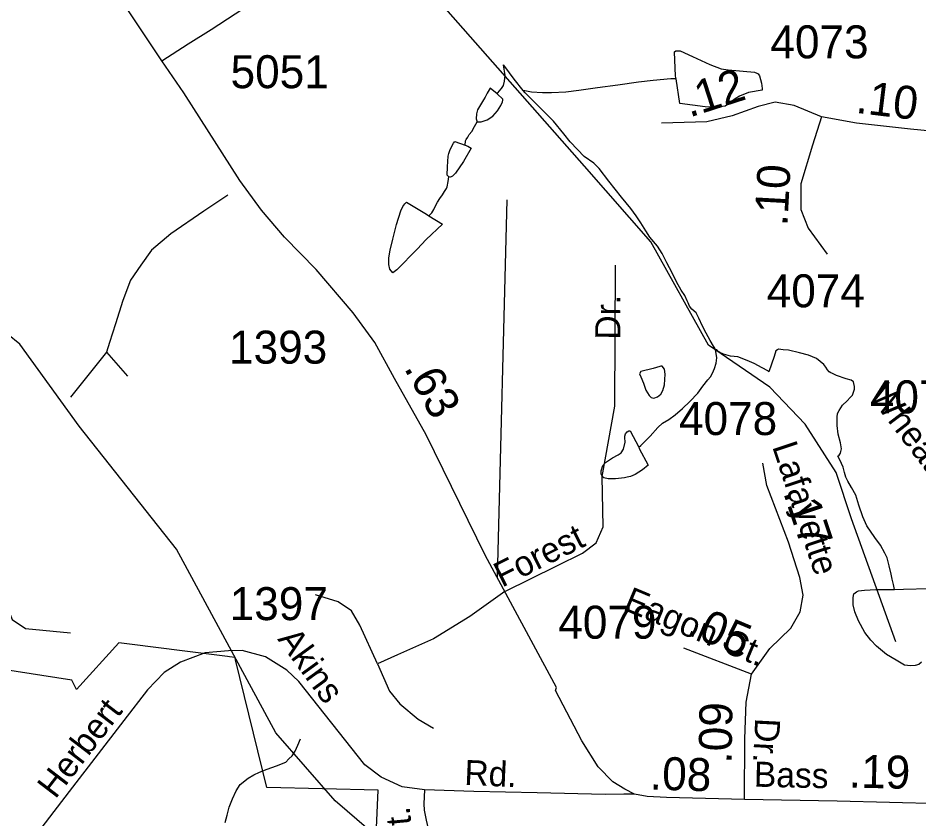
# Model space of a CAD drawing. Extents: x 2001466 to 2224147, y 644118 to 847247.
# Drawn here: x 2059578 to 2062991, y 683500 to 686536 of the extents above; entities that cross this region are included whole.
import ezdxf

# ---------------------------------------------------------------- set-up
doc = ezdxf.new("R2010")
doc.units = 0
for name, color, linetype in [('Exist Boundary Political City Limit New', 7, 'Continuous'), ('Exist Hydrographic Misc Water Feature', 7, 'Continuous'), ('Exist Road Non-System Type 51', 7, 'Continuous'), ('Exist Road Non-System Type 51 Label', 7, 'Continuous'), ('Exist Road Secondary Mileage Hundredths English Label', 7, 'Continuous'), ('Exist Road Secondary Type 51 Attributed', 7, 'Continuous'), ('Exist Road Secondary Type 51 Label', 7, 'Continuous'), ('Exist Road Secondary Type 51 Number Label', 7, 'Continuous'), ('Map Preparation Boundary City Limit Buffer Line', 7, 'Continuous')]:
    doc.layers.add(name, color=color, linetype=linetype)

msp = doc.modelspace()

# ---------------------------------------------------------------- linework, layer by layer
at = {"layer": 'Exist Boundary Political City Limit New'}
for points in [[(2059959.2, 684167.6), (2059798.8, 683990.9), (2059781, 684026.7), (2058611.8, 684208.8), (2058604, 684033.6), (2056704.1, 683944.6), (2056239.2, 683932.6), (2056313, 684129.7), (2054722.9, 684120.6)], [(2060928.9, 683323.6), (2060941.4, 683609.2), (2060520.2, 683619.2), (2060401.9, 684103.4), (2060399.8, 684112.5), (2060379.1, 684115.3), (2060370.9, 684116.2), (2060351.6, 684118.6), (2060209.2, 684136.4), (2060000, 684162.6), (2059959.2, 684167.6)]]:
    msp.add_lwpolyline(points, dxfattribs=at)
at = {"layer": 'Exist Hydrographic Misc Water Feature'}
for points in [[(2061723.1, 685974.1), (2061047.8, 686743), (2060930.9, 687066.9), (2060913.9, 687316.5), (2060779.8, 687657.2), (2060746, 687799), (2060762, 688274.4), (2060820, 688476.6), (2060795, 688674), (2060743.9, 688825.9), (2060693.9, 689125.6), (2060668.9, 689149)], [(2062070.4, 686305.7), (2062068.5, 686315.7), (2062064.4, 686408.1), (2062070.2, 686412.1), (2062086.4, 686412), (2062132.5, 686390.1), (2062198.5, 686360.2), (2062242, 686344.2), (2062268.3, 686340.2), (2062368.1, 686330.4), (2062376.5, 686326.7), (2062382.1, 686324.6), (2062386.4, 686316.7), (2062394.4, 686288.7), (2062396.6, 686268.5), (2062396.4, 686262.4), (2062344.5, 686254.5), (2062310.7, 686240.5), (2062294.5, 686230.4), (2062284.3, 686222.2), (2062268.7, 686210.4), (2062256.8, 686202.4), (2062246.5, 686200.3), (2062234.8, 686198.1), (2062180.3, 686200.2), (2062084.5, 686211.9), (2062070.4, 686305.7)], [(2061392.7, 686248.7), (2061400.7, 686258.8), (2061408.7, 686268.6), (2061416.3, 686280.8), (2061420.6, 686296.8), (2061422.6, 686318.8), (2061416.5, 686358.6)], [(2061490.7, 686261), (2061456.9, 686304.7), (2061422.4, 686352.9), (2061416.5, 686358.6)], [(2062070.4, 686305.7), (2062050.5, 686305.9), (2061984.3, 686299.7), (2061928.5, 686293.6), (2061850.4, 686281.5), (2061772.7, 686271.4), (2061702.5, 686261.3), (2061652.7, 686255.1), (2061598.8, 686253.1), (2061564.7, 686253), (2061522.5, 686254.9), (2061490.7, 686261)], [(2061392.7, 686248.7), (2061366.7, 686270.5), (2061354.8, 686250.8), (2061347, 686236.6), (2061340.6, 686226.6), (2061318.9, 686188.5), (2061315, 686172.5), (2061312.7, 686154.5), (2061317.2, 686142.5)], [(2061317.2, 686142.5), (2061321.1, 686142.7), (2061332.8, 686142.6), (2061354.8, 686150.6), (2061376.9, 686164.7), (2061394.7, 686184.7), (2061407, 686204.7), (2061412.8, 686218.8), (2061414.6, 686224.7), (2061414.4, 686228.7), (2061392.7, 686248.7)], [(2062220.3, 685280.4), (2062218, 685284.4), (2062212.1, 685292.6), (2062200, 685314.3), (2062184.4, 685342.2), (2062170.5, 685368.2), (2062156.3, 685398.4), (2062146.1, 685418.2), (2062130.1, 685432.4), (2062121.9, 685444.2), (2062116.3, 685456.4), (2062112, 685464.3), (2062103.8, 685484.2), (2062089.9, 685504.2), (2062071.6, 685536.1), (2062055.6, 685570.2), (2062035.7, 685608.1), (2062017.9, 685644), (2061999.6, 685672), (2061971.6, 685705.8), (2061955.6, 685729.7), (2061937.7, 685759.6), (2061919.5, 685785.9), (2061899.6, 685813.7), (2061863.5, 685857.7), (2061815.3, 685917.3), (2061779, 685965.4), (2061758.9, 685985.5), (2061722.8, 686011.2), (2061697, 686037.5), (2061668.9, 686067.3), (2061644.9, 686097.2), (2061606.8, 686145.3), (2061554.5, 686197), (2061498.7, 686252.9), (2061490.7, 686261)], [(2061271.1, 686054.6), (2061273.4, 686070.5), (2061275.2, 686076.3), (2061281.1, 686084.3), (2061287.1, 686094.3), (2061296.7, 686106.7), (2061307, 686124.6), (2061317.2, 686142.5)], [(2061209.4, 685934.5), (2061203.2, 685940.3), (2061205.1, 685972.5), (2061207.1, 686012.4), (2061209.2, 686022.6), (2061215.3, 686038.3), (2061227, 686062.5), (2061233, 686068.5), (2061271.1, 686054.6)], [(2061271.1, 686054.6), (2061281.1, 686050.6), (2061294.9, 686042.4), (2061264.9, 685992.6), (2061235.2, 685948.5), (2061223.3, 685936.5), (2061215.5, 685932.4), (2061209.4, 685934.5)], [(2062902.7, 684172.4), (2062734.8, 684638.4), (2062676.7, 684813.5), (2062559.9, 684996.4), (2062425.7, 685136.8), (2062192.8, 685295.9), (2061974.8, 685687.4), (2061723.1, 685974.1)], [(2061133.7, 685786.2), (2061139.9, 685792.2), (2061145.4, 685798.2), (2061153.4, 685810.4), (2061159.6, 685824.5), (2061167.3, 685838.3), (2061175.3, 685852.5), (2061185.4, 685866.4), (2061193.2, 685878.2), (2061201.2, 685890.4), (2061203.4, 685896.5), (2061207.1, 685916.2), (2061209.4, 685934.5)], [(2061079.9, 683310.6), (2060778.8, 683569.3), (2060553.8, 683826.5), (2060177.8, 684523.2), (2059809.9, 684989.9), (2059584.8, 685299.6), (2059442.9, 685414.1), (2059116.8, 685830.8), (2058824.8, 685813.8)], [(2061133.7, 685786.2), (2061185.8, 685754.4), (2061123.9, 685696.4), (2061089.8, 685660.2), (2061012.1, 685582), (2060997.8, 685570), (2060986.1, 685583.9), (2060981.8, 685601.9), (2060982, 685627.9), (2060987.9, 685656.2), (2060997.8, 685698.1), (2061011.9, 685754), (2061027.3, 685806), (2061035.5, 685822.2), (2061043.5, 685831.9), (2061049.6, 685838.3), (2061125.3, 685792.3), (2061133.7, 685786.2)], [(2061929.1, 684910), (2061937.3, 684916), (2061949.2, 684928), (2061973, 684952), (2062000.9, 684983.9), (2062018.9, 685000.2), (2062042.9, 685014), (2062066.7, 685032.3), (2062094.6, 685056.5), (2062122.7, 685082.2), (2062152.6, 685114.2), (2062172.3, 685140.4), (2062190.3, 685164.4), (2062200.4, 685176.3), (2062208.8, 685190.5), (2062216.4, 685208.3), (2062222.3, 685228.5), (2062224.4, 685248.5), (2062220.3, 685280.4)], [(2062422.5, 685195), (2062418.4, 685198.8), (2062396.6, 685210.7), (2062366.5, 685226.5), (2062340.4, 685238.6), (2062304.6, 685252.6), (2062276.5, 685254.4), (2062250, 685262.5), (2062236.3, 685268.6), (2062230.5, 685272.3), (2062224.4, 685278.5), (2062220.3, 685280.4)], [(2062682.9, 684875.6), (2062689, 684879.5), (2062692.9, 684887.5), (2062694.8, 684893.3), (2062696.8, 684903.5), (2062692.9, 684925.6), (2062684.5, 684959.3), (2062681, 684991.5), (2062680.8, 685023.2), (2062682.7, 685037.5), (2062688.4, 685049.2), (2062700.7, 685069.2), (2062718.8, 685085.6), (2062730.5, 685097.6), (2062738.5, 685107.3), (2062746.4, 685129.6), (2062746.4, 685139.3), (2062744.2, 685151.4), (2062742.1, 685157.4), (2062734.4, 685163.5), (2062714.5, 685169.3), (2062678.2, 685181.3), (2062662.6, 685189.4), (2062656.4, 685191.1), (2062650.3, 685195.3), (2062644.3, 685203.1), (2062638.4, 685213.3), (2062630.4, 685223.1), (2062602.1, 685245.2), (2062572.6, 685259), (2062538.1, 685267), (2062496.5, 685277), (2062476, 685278.9), (2062458.4, 685280.8), (2062454.2, 685278.9), (2062448.1, 685275), (2062442.4, 685252.8), (2062422.5, 685195)], [(2061984.3, 685208.2), (2061936.5, 685196), (2061932.4, 685187.7), (2061936.5, 685175.7), (2061947, 685151.9), (2061956.6, 685126.1), (2061968.5, 685106), (2061976.5, 685097.9), (2061986.9, 685095.9), (2062000.7, 685099.9), (2062012.6, 685110.3), (2062020.6, 685124.1), (2062026.7, 685146.3), (2062028.8, 685186.1), (2062026.5, 685205.9), (2062018.3, 685216.1), (2062012.4, 685216.1), (2062008.7, 685215.9), (2061984.3, 685208.2)], [(2061929.1, 684910), (2061931.2, 684904), (2061965.4, 684842), (2061943.3, 684823.9), (2061915.6, 684805.8), (2061897.3, 684798), (2061885.4, 684795.7), (2061875.4, 684794), (2061841.6, 684789.8), (2061813.5, 684789.6), (2061797.1, 684793.7), (2061791.3, 684797.8), (2061787, 684807.8), (2061787.4, 684819.5), (2061793.4, 684839.7), (2061803.4, 684851.6), (2061829.3, 684869.5), (2061851.4, 684880), (2061862.9, 684888), (2061871.3, 684901.7), (2061877.2, 684928), (2061876.8, 684945.9), (2061877, 684951.9), (2061879.1, 684959.7), (2061884.8, 684967.8), (2061891, 684971.8), (2061896.9, 684972.1), (2061929.1, 684910)], [(2062897.8, 684370.1), (2062893.9, 684389.7), (2062889.6, 684409.9), (2062885.9, 684427.9), (2062877.7, 684460), (2062869.9, 684489.9), (2062861.7, 684507.8), (2062845.5, 684537.8), (2062823.8, 684567.5), (2062793.2, 684611.9), (2062777.6, 684645.5), (2062763.3, 684689.4), (2062751.4, 684727.8), (2062735, 684757.4), (2062721.2, 684781.4), (2062713.4, 684795.6), (2062709.1, 684813.6), (2062703.2, 684833.6), (2062691.1, 684861.4), (2062682.9, 684875.6)], [(2063000.3, 684094.2), (2062990.5, 684086.4), (2062976.1, 684082), (2062958.5, 684080.3), (2062936.5, 684083.9), (2062904.1, 684101.8), (2062868.2, 684123.9), (2062830.3, 684156), (2062808, 684177.7), (2062786.2, 684207.7), (2062762, 684251.6), (2062748.3, 684285.7), (2062741.9, 684311.8), (2062741.9, 684339.8), (2062743.8, 684353.7), (2062753.6, 684361.5), (2062762, 684365.5), (2062784, 684367.9), (2062827.6, 684369.8), (2062897.8, 684370.1)], [(2062897.8, 684370.1), (2062931.8, 684371.8), (2063029.8, 684374)], [(2060362.1, 683487.4), (2060370.1, 683515.4), (2060378.1, 683545.4), (2060389.8, 683577.3), (2060403.7, 683607.2), (2060419.5, 683631.2), (2060449.5, 683655.4), (2060471.6, 683667.5), (2060491.9, 683677.4), (2060521.4, 683689.6), (2060557.5, 683701.6), (2060591.8, 683715.4), (2060603.7, 683727.8), (2060615.8, 683739.8), (2060627.2, 683757.9), (2060637.3, 683779.9), (2060647.3, 683803.9)]]:
    msp.add_lwpolyline(points, dxfattribs=at)
at = {"layer": 'Exist Road Non-System Type 51'}
for p, q in [((2061429.2, 685847.7), (2061392.3, 684417.1)), ((2059912.5, 685269.2), (2059776.1, 685098.6)), ((2059912.5, 685269.2), (2059992.1, 685178.2))]:
    msp.add_line(p, q, dxfattribs=at)
for points in [[(2060372.6, 685864.3), (2060282.1, 685803.9), (2060157, 685718.6), (2060083.1, 685656), (2060043.3, 685599.1), (2060003.5, 685542.3), (2059975.1, 685465.5), (2059946.7, 685377.3), (2059923.9, 685306.2), (2059912.5, 685269.2)], [(2061421.8, 684362.2), (2061619.2, 684459.5), (2061715.8, 684507.8), (2061768.4, 684547.6), (2061794, 684607.4), (2061791.2, 684797.9), (2061838.1, 685065.2), (2061840.9, 685599.9)], [(2061421.8, 684362.2), (2061288.8, 684268.2), (2061151.9, 684183), (2061015, 684122.1), (2060938.9, 684088.6)], [(2060938.9, 684088.6), (2060872, 684234.7), (2060841.6, 684289.5), (2060789.9, 684323), (2060704.7, 684350.4)], [(2059532.3, 684313.5), (2059555.5, 684256.8), (2059605.7, 684222.1), (2059776.8, 684206.6)], [(2060938.9, 684088.6), (2060984.6, 683985.1), (2061024.1, 683936.4), (2061094.1, 683878.5), (2061151.9, 683845.1)], [(2061118, 683610.8), (2061114.4, 683558.1), (2061115.9, 683534.1), (2061123.7, 683495.6), (2061130.8, 683462.9), (2061140.7, 683434.4), (2061155, 683394.6), (2061179.1, 683336.2), (2061193.3, 683303.5)]]:
    msp.add_lwpolyline(points, dxfattribs=at)
at = {"layer": 'Exist Road Secondary Type 51 Attributed'}
for points in [[(2060123, 686374.3), (2060221.8, 686438.6), (2060309.9, 686493.1), (2060400.7, 686552.7), (2060489.8, 686612.8), (2060530.2, 686653.2), (2060551.6, 686681.7), (2060576.5, 686719.7), (2060602.6, 686770.8), (2060613.3, 686816), (2060618.1, 686854), (2060618.1, 686893.2), (2060614.5, 686924.1), (2060606.2, 686976.3), (2060590.7, 687019.1), (2060539.7, 687090.3), (2060458.4, 687196.7)], [(2060123, 686374.3), (2060036.3, 686503.2), (2059829.6, 686816.6)], [(2061913.2, 683594.9), (2061876.2, 683613.8), (2061831, 683641.4), (2061775.8, 683698.5), (2061713, 683796.4), (2061613.9, 683987.3), (2061617.4, 683998.9), (2061347.6, 684500.2), (2061123.5, 684955.8), (2061003.6, 685170.5), (2060929.4, 685306.3), (2060847.4, 685418.4), (2060706.9, 685583.4), (2060587, 685705), (2060500.2, 685807.6), (2060418.2, 685919.8), (2060205.2, 686252.1), (2060123, 686374.3)], [(2062621, 686161.8), (2062518.4, 686204.4), (2062445.8, 686217), (2062381.1, 686201.2), (2062283.3, 686164.9), (2062187.4, 686142.8), (2062015.4, 686137.3)], [(2062621, 686161.8), (2062587, 686054.4), (2062543.6, 685908.3), (2062543.2, 685810.4), (2062571.6, 685739.3), (2062642.7, 685641.4)], [(2063141.7, 686097), (2062958.6, 686114.4), (2062753.5, 686138.1), (2062621, 686161.8)], [(2062356.6, 684048.9), (2062426.1, 684146.8), (2062505.8, 684224.2), (2062540.5, 684285.8), (2062551.5, 684348.9), (2062538.9, 684415.3), (2062496.3, 684549.5), (2062415, 684764.2), (2062399.2, 684849.5)], [(2061913.2, 683594.9), (2061873, 683594.3), (2061802.1, 683593.7), (2061544.6, 683599.5), (2061304.3, 683605.1), (2061118, 683610.8), (2061032.6, 683622.2), (2060953, 683659.2), (2060891.9, 683706.2), (2060641.8, 684022.1), (2060595.4, 684064.1), (2060515.8, 684114.8), (2060427.4, 684139.5), (2060375.3, 684138), (2060286.9, 684130.8), (2060192.8, 684094.5), (2060131.9, 684055.4), (2060068.2, 683990.2), (2059978.4, 683874.3), (2059771.3, 683604.7), (2059621.9, 683410.2)], [(2062356.6, 684048.9), (2062099.4, 684148.4)], [(2062329.2, 683574.2), (2062331.4, 683804.2), (2062336.1, 683943.1), (2062356.6, 684048.9)], [(2062329.2, 683574.2), (2062034.3, 683581.7), (2061961.5, 683586.1), (2061913.2, 683594.9)], [(2063286, 683551.6), (2063077.7, 683557.9), (2062681.2, 683567.9), (2062329.2, 683574.2)]]:
    msp.add_lwpolyline(points, dxfattribs=at)
at = {"layer": 'Map Preparation Boundary City Limit Buffer Line'}
for points in [[(2059959.2, 684167.6), (2059798.8, 683990.9), (2059781, 684026.7), (2058611.8, 684208.8), (2058604, 684033.6), (2056704.1, 683944.6), (2056239.2, 683932.6), (2056313, 684129.7), (2054722.9, 684120.6)], [(2060928.9, 683323.6), (2060941.4, 683609.2), (2060520.2, 683619.2), (2060401.9, 684103.4), (2060399.8, 684112.5), (2060379.1, 684115.3), (2060370.9, 684116.2), (2060351.6, 684118.6), (2060209.2, 684136.4), (2060000, 684162.6), (2059959.2, 684167.6)]]:
    msp.add_lwpolyline(points, dxfattribs=at)

# ---------------------------------------------------------------- texts
at = {"layer": 'Exist Road Non-System Type 51 Label'}
for s, rotation, p in [('Dr.', 89.6954, (2061859, 685317.2)), ('Forest', 26.5752, (2061411, 684376.3)), (' St.', 95.2551, (2061078.6, 683360.5))]:
    msp.add_text(s, height=95, rotation=rotation, dxfattribs=at).set_placement(p)
at = {"layer": 'Exist Road Secondary Mileage Hundredths English Label'}
for s, rotation, p in [('.12', 17.9188, (2062121.1, 686158.5)), ('.10', 353.0737, (2062748.5, 686177.3)), ('.10', 86.8209, (2062491.9, 685746.1)), ('.63', 299.1804, (2061038, 685209.9)), ('.17', 288.3673, (2062475.4, 684738.1)), ('.05', 337.2765, (2062106.6, 684201.6)), ('.09', 89.0837, (2062280.7, 683709.7)), ('.08', 358.1516, (2061969.9, 683612.4)), ('.19', 358.7298, (2062724, 683619.7))]:
    msp.add_text(s, height=125, rotation=rotation, dxfattribs=at).set_placement(p)
at = {"layer": 'Exist Road Secondary Type 51 Label'}
for s, rotation, p in [('Wheatridge Dr.', 307.3933, (2062796.7, 685106.3)), ('Lafayette', 288.3673, (2062433.9, 684912.3)), ('Eagon Ct.', 337.2765, (2061866.3, 684294.7)), ('Akins', 306.0157, (2060558.7, 684181.6)), ('Herbert', 52.5129, (2059719.1, 683573.2)), ('Dr.', 267.0735, (2062370.6, 683884.3)), ('Rd.', 357.5622, (2061267.3, 683629.6)), ('Bass', 358.7298, (2062364.7, 683623))]:
    msp.add_text(s, height=95, rotation=rotation, dxfattribs=at).set_placement(p)
at = {"layer": 'Exist Road Secondary Type 51 Number Label'}
for s, p in [('4073', (2062428, 686383.4)), ('5051', (2060382.9, 686270.2)), ('4074', (2062414, 685439.8)), ('1393', (2060377.2, 685226.3)), ('4077', (2062804.7, 685037.8)), ('4078', (2062081.7, 684955.6)), ('1397', (2060379.7, 684254.1)), ('4079', (2061624.4, 684183.8))]:
    msp.add_text(s, height=125, dxfattribs=at).set_placement(p)

doc.saveas('drawing.dxf')
